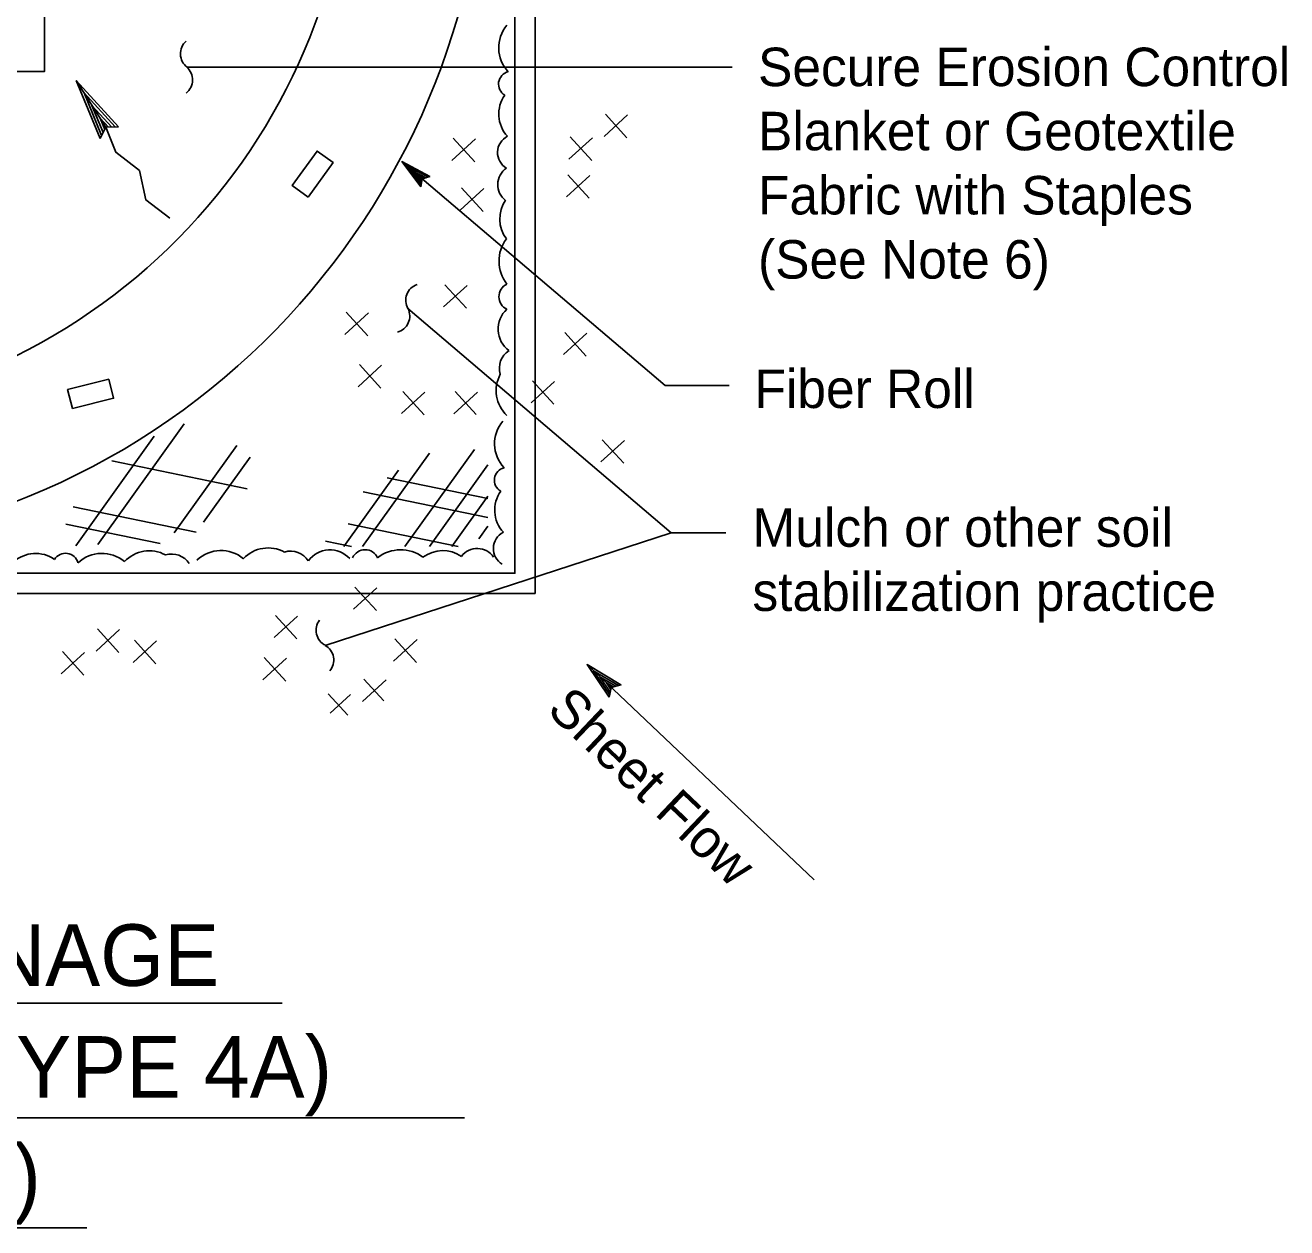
# Model space of a CAD drawing. Extents: x 6707406 to 6714471, y 1868570 to 1872341.
# Drawn here: x 6709235.1 to 6709471, y 1871409.4 to 1871634.3 of the extents above; entities that cross this region are included whole.
import ezdxf

# ---------------------------------------------------------------- set-up
doc = ezdxf.new("R2010")
doc.units = 0
for name, color, linetype in [('1 Control', 7, 'Continuous'), ('57 Undefined', 7, 'Continuous'), ('60 Nongeo Data', 7, 'Continuous'), ('62 As-Built Chng', 7, 'Continuous'), ('63 Undefined', 7, 'Continuous')]:
    doc.layers.add(name, color=color, linetype=linetype)

msp = doc.modelspace()

# ---------------------------------------------------------------- linework, layer by layer
at = {"layer": '1 Control'}
for p, q in [((6709340.19, 1871514.73), (6709340.19, 1871514.73)), ((6709346.51, 1871510.93), (6709346.51, 1871510.93)), ((6709344.3, 1871508.61), (6709344.3, 1871508.61))]:
    msp.add_line(p, q, dxfattribs=at)
msp.add_lwpolyline([(6709344.3, 1871508.61), (6709340.19, 1871514.73), (6709346.51, 1871510.93), (6709346.03, 1871510.8), (6709341.4, 1871513.58), (6709344.41, 1871509.09), (6709344.52, 1871509.57), (6709342.59, 1871512.44), (6709345.55, 1871510.67), (6709345.07, 1871510.53), (6709343.79, 1871511.3), (6709344.63, 1871510.06), (6709344.71, 1871510.43), (6709346.51, 1871510.93), (6709344.71, 1871510.43)], close=True, dxfattribs=at)
at = {"layer": '57 Undefined'}
for p, q in [((6709367.3, 1871626.48), (6709265.36, 1871626.48)), ((6709305.54, 1871608.8), (6709354.79, 1871566.89)), ((6709306.68, 1871581.3), (6709355.94, 1871539.39)), ((6709366.73, 1871566.89), (6709354.79, 1871566.89)), ((6709291.22, 1871518.28), (6709355.94, 1871539.39)), ((6709366.16, 1871539.39), (6709355.94, 1871539.39)), ((6709382.64, 1871474.43), (6709340.19, 1871514.73)), ((6709087.18, 1871451.4), (6709283.18, 1871451.4)), ((6709050.17, 1871429.96), (6709317.27, 1871429.96)), ((6709123.18, 1871409.38), (6709246.6, 1871409.38))]:
    msp.add_line(p, q, dxfattribs=at)
at = {"layer": '60 Nongeo Data'}
for p, q in [((6709305.54, 1871608.8), (6709305.54, 1871608.8)), ((6709309.09, 1871604.09), (6709309.09, 1871604.09)), ((6709310.75, 1871606.04), (6709310.75, 1871606.04))]:
    msp.add_line(p, q, dxfattribs=at)
msp.add_lwpolyline([(6709309.09, 1871604.09), (6709305.54, 1871608.8), (6709310.75, 1871606.04), (6709310.38, 1871605.92), (6709306.56, 1871607.94), (6709309.16, 1871604.48), (6709309.22, 1871604.87), (6709307.56, 1871607.08), (6709310, 1871605.79), (6709309.62, 1871605.66), (6709308.57, 1871606.22), (6709309.29, 1871605.27), (6709309.34, 1871605.57), (6709310.75, 1871606.04), (6709309.34, 1871605.57)], close=True, dxfattribs=at)
msp.add_arc((6709182.99, 1871674.08), 113.4, 20.4401, 11.3417, dxfattribs=at)
at = {"layer": '62 As-Built Chng'}
for p, q in [((6709343.37, 1871613.51), (6709347.77, 1871617.53)), ((6709343.62, 1871617.65), (6709347.64, 1871613.26)), ((6709337.04, 1871613.4), (6709341.06, 1871609)), ((6709314.9, 1871609.01), (6709319.3, 1871613.03)), ((6709315.15, 1871613.16), (6709319.17, 1871608.76)), ((6709336.79, 1871609.25), (6709341.19, 1871613.27)), ((6709336.57, 1871606.34), (6709340.59, 1871601.94)), ((6709316.7, 1871603.87), (6709320.72, 1871599.47)), ((6709336.32, 1871602.2), (6709340.72, 1871606.21)), ((6709316.45, 1871599.73), (6709320.85, 1871603.75)), ((6709313.34, 1871581.63), (6709317.74, 1871585.65)), ((6709313.59, 1871585.77), (6709317.61, 1871581.38)), ((6709294.88, 1871576.47), (6709299.28, 1871580.49)), ((6709295.13, 1871580.61), (6709299.15, 1871576.21)), ((6709335.77, 1871572.69), (6709340.16, 1871576.7)), ((6709336.02, 1871576.83), (6709340.04, 1871572.43)), ((6709297.59, 1871570.84), (6709301.61, 1871566.44)), ((6709297.34, 1871566.69), (6709301.74, 1871570.71)), ((6709329.72, 1871563.65), (6709334.12, 1871567.67)), ((6709329.97, 1871567.8), (6709333.99, 1871563.4)), ((6709305.46, 1871561.66), (6709309.86, 1871565.68)), ((6709305.71, 1871565.81), (6709309.73, 1871561.41)), ((6709315.27, 1871561.64), (6709319.67, 1871565.66)), ((6709315.52, 1871565.79), (6709319.43, 1871561.51)), ((6709343.01, 1871556.77), (6709347.03, 1871552.38)), ((6709342.76, 1871552.63), (6709347.16, 1871556.65)), ((6709296.5, 1871525.07), (6709300.89, 1871529.08)), ((6709296.75, 1871529.21), (6709300.77, 1871524.81)), ((6709281.63, 1871519.76), (6709286.03, 1871523.78)), ((6709281.88, 1871523.91), (6709285.9, 1871519.51)), ((6709248.61, 1871521.39), (6709252.63, 1871516.99)), ((6709248.36, 1871517.25), (6709252.76, 1871521.27)), ((6709255.28, 1871515.13), (6709259.68, 1871519.15)), ((6709255.53, 1871519.28), (6709259.55, 1871514.88)), ((6709304, 1871515.37), (6709308.39, 1871519.39)), ((6709304.25, 1871519.51), (6709308.27, 1871515.11)), ((6709241.79, 1871512.99), (6709246.19, 1871517.01)), ((6709242.04, 1871517.14), (6709246.06, 1871512.74)), ((6709279.54, 1871511.88), (6709283.94, 1871515.9)), ((6709279.79, 1871516.02), (6709283.81, 1871511.62)), ((6709298.2, 1871507.84), (6709302.6, 1871511.86)), ((6709298.45, 1871511.99), (6709302.15, 1871507.94)), ((6709291.78, 1871509.27), (6709295.46, 1871505.25)), ((6709292.12, 1871505.66), (6709295.93, 1871509.15))]:
    msp.add_line(p, q, dxfattribs=at)
for points in [[(6709036.13, 1871820.42), (6709330.46, 1871820.42), (6709330.46, 1871528.03), (6709036.13, 1871528.03)], [(6709040.24, 1871816.63), (6709326.68, 1871816.63), (6709326.68, 1871531.81), (6709040.24, 1871531.81)], [(6709126.63, 1871723.85), (6709238.71, 1871723.85), (6709238.71, 1871625.65), (6709126.63, 1871625.65)], [(6709288.02, 1871602.16), (6709285.03, 1871604.32), (6709289.68, 1871610.76), (6709292.67, 1871608.6)], [(6709243.91, 1871562.59), (6709243.01, 1871566.17), (6709250.72, 1871568.1), (6709251.62, 1871564.52)]]:
    msp.add_lwpolyline(points, close=True, dxfattribs=at)
msp.add_arc((6709182.99, 1871674.08), 138.36, 19.738, 11.782, dxfattribs=at)
at = {"layer": '63 Undefined'}
for p, q in [((6709249.1, 1871613.13), (6709244.64, 1871623.96)), ((6709244.64, 1871623.96), (6709252.54, 1871615.31)), ((6709249.38, 1871613.68), (6709246.11, 1871621.63)), ((6709246.11, 1871621.63), (6709251.92, 1871615.29)), ((6709249.68, 1871614.24), (6709247.58, 1871619.32)), ((6709247.58, 1871619.32), (6709251.28, 1871615.26)), ((6709249.97, 1871614.8), (6709249.09, 1871616.95)), ((6709249.09, 1871616.95), (6709250.65, 1871615.24)), ((6709250.19, 1871615.21), (6709249.1, 1871613.13)), ((6709252.54, 1871615.31), (6709250.19, 1871615.21)), ((6709264.85, 1871559.73), (6709248.67, 1871537.17)), ((6709259.22, 1871557.42), (6709244.55, 1871536.96)), ((6709274.66, 1871555.67), (6709262.96, 1871539.35)), ((6709319.12, 1871554.97), (6709306.11, 1871536.82)), ((6709251.31, 1871552.8), (6709276.6, 1871547.61)), ((6709277.14, 1871553.49), (6709268.45, 1871541.38)), ((6709310.69, 1871554.25), (6709298.19, 1871536.82)), ((6709321.62, 1871552.05), (6709310.71, 1871536.82)), ((6709304.89, 1871551.1), (6709294.66, 1871536.82)), ((6709302.78, 1871549.63), (6709321.62, 1871545.76)), ((6709298.28, 1871547.05), (6709321.62, 1871542.26)), ((6709321.62, 1871546.22), (6709314.89, 1871536.82)), ((6709244.06, 1871544.21), (6709267.08, 1871539.49)), ((6709242.68, 1871540.99), (6709260.34, 1871537.37)), ((6709295.53, 1871541.04), (6709316.1, 1871536.82)), ((6709321.62, 1871540.59), (6709319.92, 1871538.21)), ((6709291.25, 1871537.82), (6709296.13, 1871536.82))]:
    msp.add_line(p, q, dxfattribs=at)
msp.add_lwpolyline([(6709262.12, 1871598.19), (6709257.68, 1871601.63), (6709256.46, 1871607.11), (6709252.02, 1871610.55), (6709250.19, 1871615.21), (6709244.64, 1871623.96)], dxfattribs=at)
for centre, radius, start, end in [((6709330.2, 1871630.1), 6.54, 139.9986, 223.3536), ((6709267.27, 1871628.97), 3.14, 131.7958, 232.6062), ((6709263.26, 1871624.07), 3.14, 308.6008, 49.4112), ((6709326.02, 1871623.28), 2.4, 104.0578, 239.3233), ((6709329.77, 1871617.68), 6.1, 144.5002, 222.8354), ((6709326.84, 1871610.49), 3.41, 117.0211, 239.1913), ((6709327.14, 1871604.5), 3.68, 123.6905, 233.3403), ((6709330.06, 1871598.06), 6.2, 145.656, 216.6973), ((6709330.71, 1871590.18), 7, 143.3979, 217.9353), ((6709309.41, 1871582.85), 3.14, 108.8692, 209.6796), ((6709326.26, 1871583.53), 2.57, 114.5196, 245.4804), ((6709303.88, 1871579.9), 3.14, 285.6742, 26.4846), ((6709328.54, 1871577.48), 5, 132.1292, 233.705), ((6709327.66, 1871570.17), 3.88, 122.3474, 197.3796), ((6709329.54, 1871565.96), 6.36, 151.3634, 226.8458), ((6709329.42, 1871556.03), 6.54, 139.9986, 223.3536), ((6709325.25, 1871549.21), 2.4, 104.0578, 239.3233), ((6709329, 1871543.61), 6.1, 144.5002, 222.8354), ((6709326.07, 1871536.42), 3.41, 117.0211, 239.1913), ((6709237.04, 1871529.41), 6.1, 54.5002, 132.8354), ((6709242.64, 1871533.15), 2.4, 14.0578, 149.3233), ((6709249.46, 1871528.98), 6.54, 49.9986, 133.3536), ((6709258.3, 1871529.64), 6.36, 61.3634, 136.8458), ((6709271.71, 1871529.52), 6.54, 49.9986, 133.3536), ((6709280.56, 1871530.18), 6.36, 61.3634, 136.8458), ((6709284.77, 1871532.06), 3.88, 32.3474, 107.3796), ((6709292.08, 1871531.18), 5, 42.1292, 143.705), ((6709298.67, 1871533.64), 2.57, 24.5196, 155.4804), ((6709305.32, 1871529.19), 7, 53.3979, 127.9353), ((6709313.2, 1871529.84), 6.2, 55.656, 126.6973), ((6709319.64, 1871532.76), 3.68, 33.6905, 143.3403), ((6709262.51, 1871531.52), 3.88, 32.3474, 107.3796), ((6709292.63, 1871521.15), 3.14, 143.1107, 243.9212), ((6709289.67, 1871515.57), 3.14, 319.9157, 60.7262)]:
    msp.add_arc(centre, radius, start, end, dxfattribs=at)

# ---------------------------------------------------------------- texts
at = {"layer": '57 Undefined'}
for s, height, p in [('Secure Erosion Control ', 7.1998, (6709372.16, 1871622.91)), ('Blanket or Geotextile', 7.1998, (6709372.16, 1871610.91)), ('Fabric with Staples ', 7.1998, (6709372.16, 1871598.91)), ('(See Note 6)', 7.1998, (6709372.16, 1871586.91)), ('Fiber Roll', 7.2, (6709371.49, 1871562.71)), ('Mulch or other soil ', 7.1998, (6709371.12, 1871536.75)), ('stabilization practice', 7.1998, (6709371.12, 1871524.75)), ('TEMPORARY DRAINAGE', 11.5197, (6709089.06, 1871454.62)), ('INLET PROTECTION (TYPE 4A)', 11.5197, (6709065.67, 1871433.7)), ('(FIBER ROLLS)', 11.5197, (6709127.61, 1871413.44))]:
    msp.add_text(s, height=height, dxfattribs=at).set_placement(p)
msp.add_text('Sheet Flow', height=7.2, rotation=316.4904, dxfattribs=at).set_placement((6709332.42, 1871505.93))

doc.saveas('drawing.dxf')
